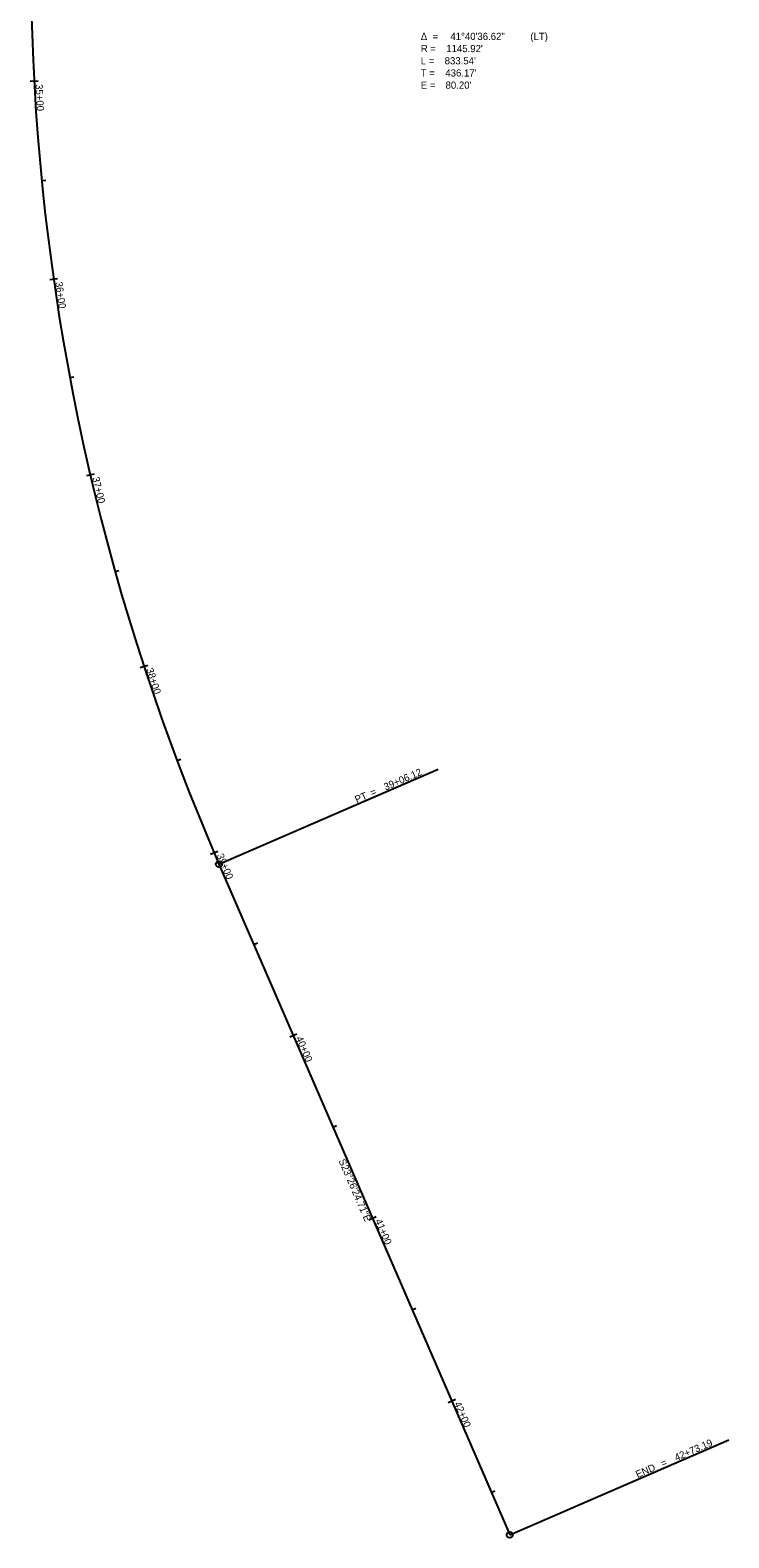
# Model space of a CAD drawing. Extents: x 1733827 to 1734180, y 466749 to 468257.
# Drawn here: x 1733829 to 1734180, y 466749 to 467506 of the extents above; entities that cross this region are included whole.
import ezdxf

# ---------------------------------------------------------------- set-up
doc = ezdxf.new("R2010")
doc.units = 0
for name, color, linetype in [('D_Roadway_Centerline', 7, 'Continuous'), ('D_Roadway_Centerline_Bearings', 7, 'Continuous'), ('D_Roadway_Centerline_CurveData', 7, 'Continuous'), ('D_Roadway_Centerline_Flags', 7, 'Continuous'), ('D_Roadway_Centerline_Text', 7, 'Continuous')]:
    doc.layers.add(name, color=color, linetype=linetype)

msp = doc.modelspace()

# ---------------------------------------------------------------- linework, layer by layer
at = {"layer": 'D_Roadway_Centerline'}
msp.add_line((1733923.39, 467086.88), (1734069.41, 466750.09), dxfattribs=at)
msp.add_arc((1734974.74, 467542.71), 1145.92, 161.76336, 203.4402, dxfattribs=at)
at = {"layer": 'D_Roadway_Centerline_Flags'}
for p, q in [((1733923.39, 467086.88), (1734033.48, 467134.61)), ((1734033.48, 467134.61), (1734033.48, 467134.61)), ((1733923.39, 467086.88), (1733923.39, 467086.88)), ((1734069.41, 466750.09), (1734179.5, 466797.83)), ((1734179.5, 466797.83), (1734179.5, 466797.83)), ((1734069.41, 466750.09), (1734069.41, 466750.09))]:
    msp.add_line(p, q, dxfattribs=at)
for centre in [(1733923.39, 467086.88), (1734069.41, 466750.09)]:
    msp.add_circle(centre, 1.5, dxfattribs=at)
at = {"layer": 'D_Roadway_Centerline_Text'}
for p, q in [((1733832.54, 467480.17), (1733828.55, 467479.95)), ((1733834.36, 467430.21), (1733836.36, 467430.4)), ((1733842.34, 467380.86), (1733838.38, 467380.29)), ((1733848.5, 467331.24), (1733850.48, 467331.62)), ((1733860.75, 467282.78), (1733856.86, 467281.87)), ((1733871.22, 467233.89), (1733873.15, 467234.43)), ((1733887.65, 467186.68), (1733883.85, 467185.43)), ((1733902.33, 467138.89), (1733904.21, 467139.6)), ((1733922.82, 467093.29), (1733919.14, 467091.71)), ((1733940.84, 467046.62), (1733942.69, 467047.41)), ((1733962.58, 467001.54), (1733958.91, 466999.95)), ((1733980.62, 466954.87), (1733982.47, 466955.67)), ((1734002.35, 466909.79), (1733998.69, 466908.2)), ((1734020.4, 466863.12), (1734022.24, 466863.92)), ((1734042.13, 466818.05), (1734038.46, 466816.46)), ((1734060.18, 466771.37), (1734062.02, 466772.17))]:
    msp.add_line(p, q, dxfattribs=at)

# ---------------------------------------------------------------- texts
at = {"layer": 'D_Roadway_Centerline_Bearings'}
msp.add_text('S23°26\'24.71"E', height=3.6, rotation=293.4402, dxfattribs=at).set_placement((1733983.37, 466937.96))
at = {"layer": 'D_Roadway_Centerline_CurveData'}
for s, p in [('Δ  = ', (1734024.76, 467500.81)), ('R = ', (1734024.76, 467494.69)), ("1145.92'", (1734037.56, 467494.69)), ('41°40\'36.62"', (1734039.64, 467500.81)), (' (LT)', (1734078.45, 467500.81)), ('L = ', (1734024.76, 467488.57)), ("833.54'", (1734036.76, 467488.57)), ('T = ', (1734024.76, 467482.45)), ("436.17'", (1734037.1, 467482.45)), ('E = ', (1734024.76, 467476.33)), ("80.20'", (1734037.2, 467476.33))]:
    msp.add_text(s, height=3.6, dxfattribs=at).set_placement(p)
at = {"layer": 'D_Roadway_Centerline_Flags'}
for s, p in [('39+06.12', (1734007.11, 467123.83)), ('PT', (1733992.58, 467117.53)), (' = ', (1733999.04, 467120.33)), ('42+73.19', (1734153.13, 466787.05)), (' = ', (1734145.07, 466783.55)), ('END', (1734133.67, 466778.61))]:
    msp.add_text(s, height=3.6, rotation=23.4402, dxfattribs=at).set_placement(p)
at = {"layer": 'D_Roadway_Centerline_Text'}
for s, rotation, p in [('35+00', 273.1344, (1733831.22, 467478.53)), ('36+00', 278.13438, (1733841.16, 467379.11)), ('37+00', 283.13436, (1733859.74, 467280.94)), ('38+00', 288.13434, (1733886.79, 467184.76)), ('39+00', 293.13432, (1733922.13, 467091.3)), ('40+00', 293.4402, (1733961.9, 466999.55)), ('41+00', 293.4402, (1734001.68, 466907.8)), ('42+00', 293.4402, (1734041.46, 466816.05))]:
    msp.add_text(s, height=3.6, rotation=rotation, dxfattribs=at).set_placement(p)

doc.saveas('drawing.dxf')
